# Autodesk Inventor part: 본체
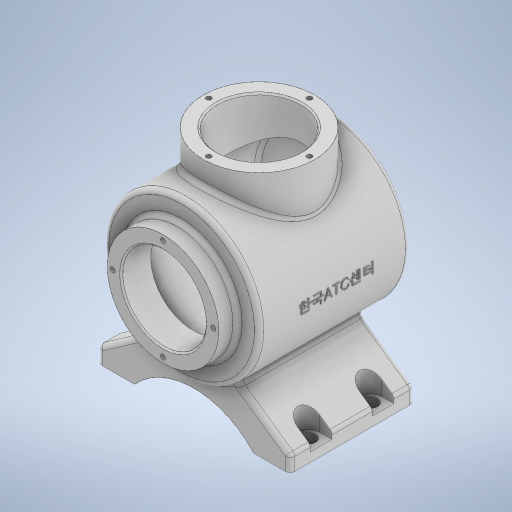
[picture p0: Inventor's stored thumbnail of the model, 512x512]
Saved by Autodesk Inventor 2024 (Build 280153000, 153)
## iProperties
Created: 2023-08
Part Number: 본체
Material: 일반
Document SubType Name: Modeling
Designer: Owner
Density: 1 g/cm^3
Appearance: 기본값
Mass: 479.566 g
Surface Area: 1065.22 cm^2
Volume: 479.566 cm^3
Author: Owner
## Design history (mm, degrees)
sketch "스케치1"
  geometry: L1 (0, 60)-(0, -60); L2 (50, -48.336)-(50, 48); L3 (50, 48)-(36, 48); L4 (36, 48)-(36, 60); L5 (43, -43.887)-(43, 41); L6 (43, 41)-(27, 41); L7 (27, 41)-(27, 60); L8 (36, 60)-(27, 60); A1 r 113 centre (0, 53) between (0, -60) and (50, -48.336); A2 r 106 centre (0, 53) between (0, -53) and (43, -43.887); 3 further points
  constraints: 16 end point, 4 perpendicular, 4 point on circle, 2 centre point, 2 midpoint, 2 vertical, 1 coincident, 1 horizontal, 1 horizontal alignment, 1 point on line, 1 vertical alignment
  dimensions: "d0" = 120 distance of L1.start L1.end; "d4" = 113 radius of A1; "d5" = 100 diameter of L2 L1; "d6" = 72 diameter of L4 L1; "d7" = 7 radial gap between concentric circles of A1 A2; "d8" = 86 diameter of L5 L1; "d9" = 54 diameter of L7 L1; "d10" = 19 distance of L6.end L7.end; "d11" = 108 vertical distance of L1.end L3.end
revolve "회전1" sketch "스케치1" stored, may be unused: angle "d12" = 90 deg
node "작업 평면1"
sketch "스케치2"
  geometry: L1 (-26.694, -42.278)-(-62, -67); L2 (-62, -67)-(-62, -77); L3 (-62, -77)-(-38.5, -77); L4 (38.5, -77)-(62, -77); L5 (62, -77)-(62, -67); L6 (62, -67)-(26.694, -42.278); A1 r 50 centre (0, 0) between (26.694, -42.278) and (-26.694, -42.278) reference; A2 r 52.096 centre (0, -112.096) between (38.5, -77) and (-38.5, -77); 5 further points
  constraints: 12 end point, 4 point on circle, 3 equal length, 2 perpendicular, 1 centre point, 1 horizontal, 1 vertical, 1 vertical alignment, 2 other
  dimensions: "d14" = 55 deg angle of L6 L5; "d15" = 77 distance from line of point (0, 0) L4; "d16" = 10 distance of L4.end L5.end; "d17" = 77 distance of L4.start L3.end; "d19" = 124 distance of L4.end L2.end; "d20" = 55 deg angle of L1 L2; "d21" = 17 vertical distance of L3.end point (0, -60)
extrude "돌출1" join sketch "스케치2" distance "d22" = 80; taper "d23" = 0 deg
node "작업 평면2"
sketch "스케치3"
  geometry: L1 (2.5, 20)-(74.5, 20) reference; C1 r 36 at (38.5, -42); 2 further points
  constraints: 1 centre point, 1 midpoint, 1 vertical alignment
  dimensions: "d25" = 72 diameter of C1; "d26" = 62 distance from line of L1 C1.centre
extrude "돌출2" join sketch "스케치3" stored distance "d27" = 80; taper "d28" = 0 deg
sketch "스케치4"
  geometry: C1 r 36 at (0, 0) reference; C2 r 27 at (0, 0); 1 further point
  constraints: 1 centre point, 1 coincident
  dimensions: "d29" = 54 diameter of C2
extrude "돌출3" cut sketch "스케치4" stored distance "d30" = 10; taper "d31" = 0 deg
sketch "스케치5"
  geometry: L1 (23.5, 0)-(23.5, -80) reference; L2 (0, 0)-(23.5, 0) reference; 3 further points
  dimensions: "d32" = 8 distance from line of point (15.5, -20) L1; "d33" = 20 distance from line of L2 point (15.5, -20); "d34" = 40 distance of point (15.5, -20) point (15.5, -60); "d35" = 8 distance from line of L1 point (15.5, -60)
hole "구멍1" sketch "스케치5" at (15.5, -20), (15.5, -60) diameter "d36" = 9; stored, may be unused: countersink angle "d40" = 90 deg, drill point angle "d42" = 0 deg; dims "d37" = 8, "d38" = 4, "d39" = 2, "d41" = 6
node "작업 평면3"
sketch "스케치6"
  geometry: L1 (-15.5, -13)-(-23.5, -13); L2 (-23.5, 0)-(-23.5, -80) reference; L3 (-15.5, -27)-(-23.5, -27); L4 (-15.5, -53)-(-23.5, -53); L5 (-15.5, -67)-(-23.5, -67); C1 r 4.5 at (-15.5, -20) reference; C2 r 4.5 at (-15.5, -60) reference; A1 r 7 centre (-15.5, -20) between (-15.5, -13) and (-15.5, -27); A2 r 7 centre (-15.5, -60) between (-15.5, -53) and (-15.5, -67); 1 further point
  constraints: 8 end point, 4 point on circle, 4 point on line, 4 tangent, 2 centre point, 2 coincident, 2 perpendicular, 1 horizontal, 1 parallel
  dimensions: "d44" = 14 diameter of A1; "d45" = 14 diameter of A2
extrude "돌출4" cut sketch "스케치6" stored distance "d46" = 10; taper "d47" = 0 deg
sketch "스케치7"
  geometry: 2 further points
  constraints: 1 vertical alignment
  dimensions: "d48" = 32.5 distance of point (0, 32.5) point (0, 0)
hole "구멍2" sketch "스케치7" at (0, 32.5) diameter "d49" = 3.242; stored, may be unused: countersink angle "d53" = 90 deg, drill point angle "d55" = 118 deg; dims "d50" = 8, "d51" = 4, "d52" = 2, "d54" = 10
sketch "스케치8"
  geometry: C1 r 27 at (0, 0) reference; C2 r 36 at (0, 0) reference; 2 further points
  constraints: 1 horizontal alignment
  dimensions: "d59" = 32.5 distance of point (-32.5, 0) C1.centre
hole "구멍3" sketch "스케치8" at (-32.5, 0) diameter "d60" = 3.242; stored, may be unused: countersink angle "d64" = 90 deg, drill point angle "d66" = 118 deg; dims "d61" = 8, "d62" = 4, "d63" = 2, "d65" = 10
node "작업 평면4"
sketch "스케치9"
  geometry: L1 (-36, 60.168)-(36, 60.168) reference; 3 further points
  constraints: 1 midpoint, 1 vertical alignment, 1 other
  dimensions: "d70" = 62 distance from line of L1 point (0, -1.832)
feature "엠보싱1" sketch "스케치9" dims "d0" = 120, "d4" = 113, "d5" = 100, "d6" = 72, "d7" = 7, "d8" = 86, "d9" = 54, "d10" = 19, "d11" = 108, "d14" = 55 deg, "d15" = 77, "d16" = 10, "d17" = 77, "d19" = 124, "d20" = 55 deg, "d21" = 17, "d71" = 0.5, "d72" = 0
fillet "모깎기1" dims "d73" = 3
fillet "모깎기2" dims "d74" = 3
fillet "모깎기3" dims "d75" = 3
fillet "모깎기4" dims "d76" = 3
chamfer "모따기1" distance "d77" = 1; stored, may be unused: second distance "d78" = 2, angle "d79" = 45 deg
fillet "모깎기5" dims "d80" = 3
feature "̫耀̭耀̯耀̱耀̳耀̵耀̷耀̹耀" dims "d0" = 120, "d4" = 113, "d5" = 100, "d6" = 72, "d7" = 7, "d8" = 86, "d9" = 54, "d10" = 19, "d11" = 108, "d12" = 90 deg, "d13" = -20, "d14" = 55 deg, "d15" = 77, "d16" = 10, "d17" = 77, "d19" = 124, "d20" = 55 deg, "d21" = 17, "d22" = 80, "d23" = 0, "d24" = -142, "d25" = 72, "d26" = 62, "d27" = 80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
node "솔리드1"
mirror "미러1"
pattern_circular "원형 패턴1" dims angle "d57" = 360 deg
pattern_circular "원형 패턴2" dims angle "d68" = 360 deg
node "투영된 루프1"
feature "A9D066F2-1C7D-4E18-AEED-F7BC21143FA4" dims "d36" = 9, "d37" = 8, "d38" = 4, "d39" = 2, "d40" = 90 deg, "d41" = 6, "d42" = 0
